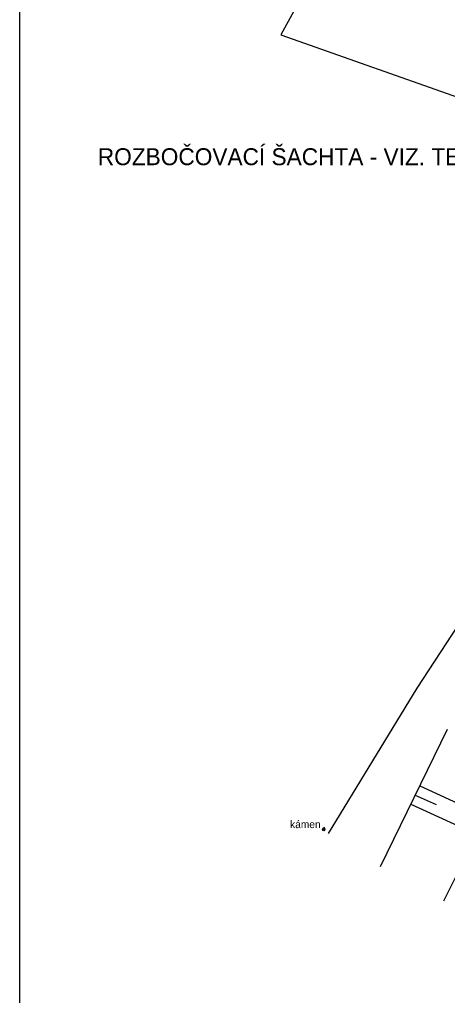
# Model space of a CAD drawing. Extents: x -517788 to -517166, y -1177087 to -1176790.
# Drawn here: x -517375.9 to -517350.6, y -1176878.7 to -1176821.1 of the extents above; entities that cross this region are included whole.
import ezdxf

# ---------------------------------------------------------------- set-up
doc = ezdxf.new("R2010")
doc.units = 0
for name, color, linetype in [('chodníky_obrubnik_schody', 7, 'Continuous'), ('hrany svahu', 7, 'Continuous'), ('mapove znacky', 7, 'Continuous'), ('označení lomového bodu', 7, 'Continuous'), ('porost', 7, 'Continuous'), ('Povrchy_popis', 7, 'Continuous'), ('šrafy', 7, 'Continuous')]:
    doc.layers.add(name, color=color, linetype=linetype)

msp = doc.modelspace()

# ---------------------------------------------------------------- linework, layer by layer
at = {"layer": 'chodníky_obrubnik_schody'}
msp.add_line((-517346.568, -1176864.44), (-517350.878, -1176873.11), dxfattribs=at)
at = {"layer": 'hrany svahu'}
msp.add_line((-517354.608, -1176871.06), (-517350.648, -1176862.97), dxfattribs=at)
msp.add_lwpolyline([(-517325.778, -1176823.62), (-517334.418, -1176819.69), (-517337.708, -1176818.07), (-517345.168, -1176814.76), (-517349.438, -1176812.59), (-517351.728, -1176812), (-517354.598, -1176812.57), (-517356.288, -1176814.32), (-517360.478, -1176821.97)], dxfattribs=at)
at = {"layer": 'mapove znacky'}
for radius in [0.0683, 0.0119]:
    msp.add_circle((-517357.948, -1176868.9), radius, dxfattribs=at)
msp.add_arc((-517357.948, -1176868.846), 0.0652, 339.29907, 201.87982, dxfattribs=at)
at = {"layer": 'označení lomového bodu'}
msp.add_line((-517375.912, -1176790.222), (-517375.912, -1176938.722), dxfattribs=at)
at = {"layer": 'porost'}
for p, q in [((-517360.478, -1176821.97), (-517348.798, -1176826.1)), ((-517345.088, -1176849.23), (-517352.448, -1176860.54)), ((-517352.448, -1176860.54), (-517357.698, -1176869.11))]:
    msp.add_line(p, q, dxfattribs=at)
at = {"layer": 'šrafy'}
for p, q in [((-517352.282, -1176866.309), (-517348.385, -1176868.096)), ((-517352.546, -1176866.848), (-517351.325, -1176867.408)), ((-517352.81, -1176867.387), (-517348.92, -1176869.171))]:
    msp.add_line(p, q, dxfattribs=at)

# ---------------------------------------------------------------- texts
at = {"layer": 'označení lomového bodu'}
msp.add_text('ROZBOČOVACÍ ŠACHTA - VIZ. TECHNICKÁ ZPRÁVA', height=1, rotation=360, dxfattribs=at).set_placement((-517371.289, -1176829.67))
at = {"layer": 'Povrchy_popis'}
msp.add_text('kámen', height=0.45, dxfattribs=at).set_placement((-517359.941, -1176868.802))

doc.saveas('drawing.dxf')
